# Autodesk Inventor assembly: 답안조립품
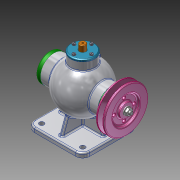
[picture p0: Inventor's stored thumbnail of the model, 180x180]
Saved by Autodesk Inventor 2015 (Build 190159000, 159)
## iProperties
Created: 2025-08
Part Number: 답안조립품
Document SubType Name: Assembly
Designer: USER
Author: USER
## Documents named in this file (15)
- C:\Users\USER\Desktop\750808V1015\답안조립품.iam
- C:\Users\USER\Desktop\750808V1015\답안본체.ipt
- C:\Users\USER\Desktop\750808V1015\가져온 구성요소\V-벨트풀리\V-벨트풀리.ipt
- C:\Users\USER\Desktop\750808V1015\가져온 구성요소\너트 M8\너트 M8.ipt
- C:\Users\USER\Desktop\750808V1015\가져온 구성요소\뒤커버\뒤커버.ipt
- C:\Users\USER\Desktop\750808V1015\가져온 구성요소\베어링- 6202\베어링- 6202.ipt
- C:\Users\USER\Desktop\750808V1015\가져온 구성요소\볼트 M4 x 12\볼트 M4 x 12.ipt
- C:\Users\USER\Desktop\750808V1015\가져온 구성요소\볼트 M4 x 16\볼트 M4 x 16.ipt
- C:\Users\USER\Desktop\750808V1015\가져온 구성요소\상부커버\상부커버.ipt
- C:\Users\USER\Desktop\750808V1015\가져온 구성요소\슬라이드\슬라이드.ipt
- C:\Users\USER\Desktop\750808V1015\가져온 구성요소\앞커버\앞커버.ipt
- C:\Users\USER\Desktop\750808V1015\가져온 구성요소\오일실 15 30 7\오일실 15 30 7.ipt
- C:\Users\USER\Desktop\750808V1015\가져온 구성요소\칼라\칼라.ipt
- C:\Users\USER\Desktop\750808V1015\가져온 구성요소\키 4 x 4 x 12\키 4 x 4 x 12.ipt
- C:\Users\USER\Desktop\750808V1015\가져온 구성요소\편심축\편심축.ipt
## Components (1 placed, 1 different names)
1. V-벨트풀리:1
